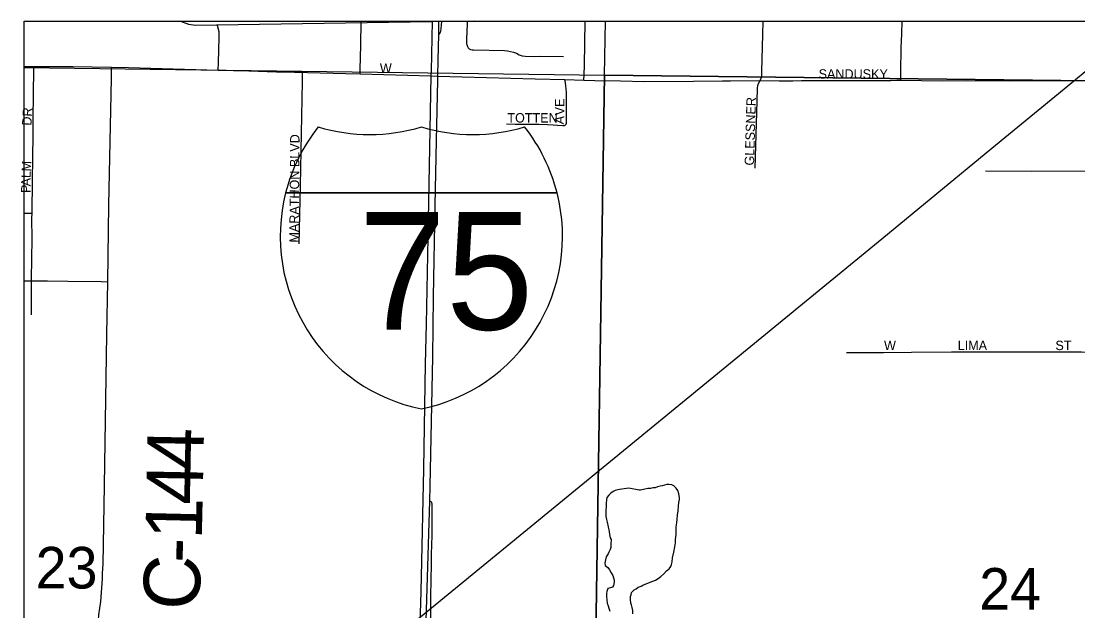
# Model space of a CAD drawing. Extents: x 0 to 68, y 0 to 52.9.
# Drawn here: x 41.101 to 42.505, y 41.224 to 42.008 of the extents above; entities that cross this region are included whole.
import ezdxf

# ---------------------------------------------------------------- set-up
doc = ezdxf.new("R2010")
doc.units = 0
for name, color, linetype in [('Default', 7, 'Continuous'), ('GM_X_County_Road', 7, 'Continuous'), ('GM_X_County_Road_Text', 7, 'Continuous'), ('GM_X_Minor_Lake', 7, 'Continuous'), ('GM_X_Township_Subdivision', 7, 'Continuous'), ('GM_X_Township_Subdivision_Text', 7, 'Continuous')]:
    doc.layers.add(name, color=color, linetype=linetype)

msp = doc.modelspace()

# ---------------------------------------------------------------- linework, layer by layer
at = {"layer": 'Default'}
for p, q in [((41.1051, 32.7683), (41.1051, 42.0083)), ((41.1051, 42.0083), (50.3451, 42.0083)), ((41.4527, 41.7799), (41.8134, 41.7799)), ((41.8134, 41.7799), (41.4527, 41.7799)), ((41.8134, 41.7799), (41.4527, 41.7799))]:
    msp.add_line(p, q, dxfattribs=at)
for points in [[(41.1051, 40.7827), (41.6098, 41.1982), (42.245, 41.7191), (42.3911, 41.8395), (42.4919, 41.9222), (42.5252, 41.9497), (42.5507, 41.971), (42.5671, 41.9855), (42.5837, 42.0005), (42.5919, 42.0083)], [(41.5517, 41.9382), (41.5517, 41.9445), (41.5525, 41.9761), (41.553, 42.0083)], [(41.6308, 41.1995), (41.6324, 41.2337), (41.6333, 41.2697), (41.6363, 41.4133), (41.6387, 41.5527), (41.6397, 41.6056), (41.642, 41.7205), (41.6462, 41.9354), (41.6463, 41.942), (41.6477, 42.0083)], [(41.655, 41.9298), (41.6551, 41.9353), (41.6555, 41.9562), (41.6563, 41.9905), (41.6564, 42.0083)], [(41.6563, 41.9905), (41.6572, 41.9913), (41.6576, 41.9921), (41.6579, 41.9925), (41.6581, 41.993), (41.6583, 41.9935), (41.6585, 41.9941), (41.6587, 41.995), (41.6589, 41.9958), (41.6592, 41.9974), (41.6594, 41.9988), (41.6598, 42.0027), (41.6602, 42.0083)], [(41.6938, 42.0081), (41.6938, 42.0048), (41.6929, 41.9842), (41.693, 41.98), (41.6932, 41.9781), (41.6934, 41.9771), (41.6937, 41.9761), (41.6942, 41.9745), (41.6947, 41.9736), (41.6954, 41.9727), (41.6965, 41.9716), (41.6973, 41.9711), (41.6985, 41.9706), (41.7004, 41.9703), (41.7025, 41.9701), (41.7436, 41.9694), (41.7476, 41.9688), (41.7556, 41.9671), (41.7593, 41.9655), (41.763, 41.9635), (41.7668, 41.9622), (41.7708, 41.9617), (41.783, 41.9613), (41.7913, 41.9615), (41.822, 41.9611)], [(41.8489, 41.9297), (41.8492, 41.9372), (41.8497, 41.9495), (41.8506, 42.0083)], [(43.2047, 42.0083), (43.2028, 41.9209), (41.8762, 41.9363), (41.8775, 42.0083)], [(42.0833, 41.9292), (42.0845, 41.9326), (42.0852, 41.9356), (42.0855, 41.9381), (42.0856, 41.9413), (42.0868, 41.9903), (42.0872, 42.0083)], [(42.27, 41.9296), (42.2702, 41.9407), (42.2707, 41.9729), (42.2713, 41.9914), (42.2718, 42.0083)], [(41.1051, 41.9468), (41.8762, 41.9363), (41.8559, 40.6193), (41.1051, 40.6295)], [(41.4708, 41.7124), (41.4725, 41.7897), (41.475, 41.9281), (41.4752, 41.9403)], [(41.5327, 41.9387), (41.5517, 41.9382)], [(41.5517, 41.9382), (41.6462, 41.9354), (41.6551, 41.9353), (41.7844, 41.9316), (41.8235, 41.9306)], [(41.6441, 41.3706), (41.6447, 41.3903), (41.6482, 41.5619), (41.649, 41.6416), (41.6515, 41.7634), (41.6533, 41.8495), (41.655, 41.9298)], [(41.7461, 41.8716), (41.758, 41.8713), (41.7791, 41.8713), (41.7896, 41.8713), (41.8006, 41.8708), (41.808, 41.8703), (41.8138, 41.8698), (41.8212, 41.8694), (41.8223, 41.8694), (41.8232, 41.8696), (41.8239, 41.8699), (41.8246, 41.8703), (41.8249, 41.8707), (41.8253, 41.8712), (41.8255, 41.8718), (41.8257, 41.8724), (41.8258, 41.8731), (41.8259, 41.8745), (41.8259, 41.8761), (41.8259, 41.8815), (41.8258, 41.9017), (41.8257, 41.9136), (41.8254, 41.9179), (41.8251, 41.9221), (41.8245, 41.9262), (41.8235, 41.9306)], [(41.8235, 41.9306), (41.8489, 41.9297)], [(41.8489, 41.9297), (41.8634, 41.9293), (41.8976, 41.9288)], [(41.8976, 41.9288), (41.929, 41.9282), (41.9946, 41.9285), (42.0332, 41.9289)], [(42.0332, 41.9289), (42.0438, 41.929), (42.0833, 41.9292)], [(42.0765, 41.8127), (42.0791, 41.9021), (42.0795, 41.9192), (42.08, 41.9227), (42.0811, 41.9255), (42.0833, 41.9292)], [(42.0833, 41.9292), (42.1085, 41.9288), (42.1266, 41.929), (42.1381, 41.9292), (42.1952, 41.9294), (42.2568, 41.9294), (42.2646, 41.9296), (42.27, 41.9296)], [(42.27, 41.9296), (42.325, 41.9289), (42.3571, 41.9294), (42.4144, 41.9291), (42.5123, 41.9293), (42.5503, 41.9291)], [(42.3827, 41.8091), (42.4441, 41.8088), (42.548, 41.8093)], [(42.1979, 41.5678), (42.2225, 41.5677), (42.2471, 41.5678), (42.2841, 41.5681), (42.3375, 41.5689), (42.4073, 41.5685), (42.51, 41.5687), (42.5299, 41.5684), (42.544, 41.5683)], [(41.6405, 41.2397), (41.6441, 41.3706)], [(41.6456, 41.2439), (41.6465, 41.2866), (41.6467, 41.2953), (41.6466, 41.2996), (41.6472, 41.3244), (41.6475, 41.3654), (41.6473, 41.3667), (41.6471, 41.3676), (41.6468, 41.3683), (41.6464, 41.3688), (41.6459, 41.3695), (41.6453, 41.3699), (41.6441, 41.3706)], [(41.6392, 41.2065), (41.6393, 41.2074), (41.6394, 41.2109), (41.6405, 41.2397)], [(41.6456, 41.2117), (41.6454, 41.2176), (41.6456, 41.233), (41.6456, 41.2428), (41.6456, 41.2439)]]:
    msp.add_lwpolyline(points, dxfattribs=at)
msp.add_lwpolyline([(41.8762, 41.9363), (43.2028, 41.9209), (43.183, 40.6024), (41.8559, 40.6193)], close=True, dxfattribs=at)
for centre, start, end in [((41.6799, 41.7224), 141.669, 165.8066), ((41.5645, 42.0919), 253.0091, 286.9909), ((41.7015, 42.0919), 253.0091, 286.9909), ((41.5862, 41.7224), 14.1934, 38.331), ((41.6799, 41.7224), 165.8066, 258.463), ((41.5862, 41.7224), 281.537, 14.1934)]:
    msp.add_arc(centre, 0.2344, start, end, dxfattribs=at)
at = {"layer": 'GM_X_County_Road'}
for points in [[(41.1051, 41.9482), (41.1179, 41.9481)], [(41.1179, 41.9481), (41.1701, 41.9479), (41.2214, 41.9472)], [(41.2164, 41.6619), (41.2179, 41.7639), (41.2211, 41.932), (41.2214, 41.9472)], [(41.2214, 41.9472), (41.2439, 41.9468), (41.3632, 41.943)], [(41.3632, 41.943), (41.4037, 41.9421), (41.4406, 41.941), (41.45, 41.9408)], [(41.45, 41.9408), (41.4645, 41.9405)], [(41.4645, 41.9405), (41.4752, 41.9403)], [(41.4752, 41.9403), (41.4816, 41.9402), (41.5327, 41.9387)], [(41.1841, 41.1549), (41.1872, 41.1611), (41.1888, 41.1647), (41.1919, 41.1728), (41.1939, 41.1785), (41.1964, 41.1855), (41.1982, 41.1914), (41.2019, 41.2056), (41.2043, 41.2166), (41.2046, 41.2192), (41.2072, 41.2368), (41.2092, 41.2671), (41.2094, 41.2743), (41.21, 41.2866), (41.2122, 41.3909), (41.2153, 41.5917), (41.2164, 41.6619)]]:
    msp.add_lwpolyline(points, dxfattribs=at)
at = {"layer": 'GM_X_Minor_Lake'}
for points in [[(41.9225, 41.385), (41.9085, 41.3873), (41.9055, 41.3869), (41.9024, 41.3864), (41.8994, 41.386), (41.8964, 41.3856), (41.8939, 41.3851), (41.8904, 41.3842), (41.8878, 41.3832), (41.8848, 41.3808), (41.8822, 41.3783), (41.8796, 41.3749), (41.8791, 41.3719), (41.8785, 41.3674), (41.8784, 41.3634), (41.8783, 41.3573), (41.8781, 41.3503), (41.879, 41.3458), (41.88, 41.3423), (41.8827, 41.3297), (41.8831, 41.3257), (41.8841, 41.3216), (41.885, 41.3191), (41.8849, 41.3131), (41.8848, 41.3086), (41.8838, 41.3061), (41.8822, 41.3026), (41.8811, 41.3001), (41.8785, 41.2962), (41.8775, 41.2922), (41.8769, 41.2877), (41.8773, 41.2846), (41.8808, 41.2821), (41.8832, 41.279), (41.8851, 41.275), (41.8876, 41.2714), (41.8894, 41.2653), (41.8894, 41.2623), (41.8883, 41.2583), (41.8868, 41.2559), (41.8842, 41.2549), (41.8807, 41.254), (41.8796, 41.25), (41.8791, 41.2475), (41.879, 41.2435), (41.8794, 41.239), (41.8798, 41.2344), (41.8812, 41.2309), (41.8822, 41.2279), (41.8836, 41.2238)], [(41.9696, 41.3094), (41.9707, 41.3149), (41.9708, 41.3194), (41.9714, 41.3259), (41.9715, 41.3309), (41.9716, 41.3359), (41.9723, 41.3414), (41.9729, 41.3464), (41.9735, 41.3514), (41.9741, 41.3574), (41.9747, 41.3634), (41.9753, 41.3684), (41.9759, 41.3724), (41.976, 41.3749), (41.975, 41.38), (41.9736, 41.3845), (41.9717, 41.3876), (41.9687, 41.3906), (41.9658, 41.3917), (41.9618, 41.3923), (41.9592, 41.3923), (41.9562, 41.3914), (41.9532, 41.3904), (41.9502, 41.39), (41.9466, 41.3891), (41.9436, 41.3881), (41.9406, 41.3877), (41.9376, 41.3872), (41.9341, 41.3868), (41.924, 41.385), (41.923, 41.385), (41.9225, 41.385)], [(41.9141, 41.2202), (41.9142, 41.2247), (41.9133, 41.2288), (41.9124, 41.2323), (41.9114, 41.2348), (41.911, 41.2393), (41.9111, 41.2433), (41.9116, 41.2458), (41.9122, 41.2488), (41.9158, 41.2523), (41.9183, 41.2537), (41.9209, 41.2557), (41.9249, 41.2571), (41.9274, 41.2586), (41.9305, 41.26), (41.9406, 41.2638), (41.9441, 41.2652), (41.9477, 41.2672), (41.9512, 41.2701), (41.9553, 41.2735), (41.9589, 41.2775), (41.9625, 41.2804), (41.9646, 41.2834), (41.9656, 41.2859), (41.9662, 41.2894), (41.9668, 41.2949), (41.9685, 41.3024), (41.9696, 41.3094)]]:
    msp.add_lwpolyline(points, dxfattribs=at)
at = {"layer": 'GM_X_Township_Subdivision'}
for points in [[(41.7038, 42.0083), (41.3323, 42.0024), (41.3242, 42.0037), (41.3122, 42.0083)], [(41.3632, 41.943), (41.3635, 41.953), (41.3644, 41.9871), (41.3644, 41.9942), (41.3621, 42.0026)], [(41.1157, 41.753), (41.1161, 41.797), (41.1171, 41.8568), (41.1172, 41.8691), (41.1177, 41.92), (41.1179, 41.9354), (41.1179, 41.9481)], [(41.1051, 41.7531), (41.1157, 41.753)], [(41.115, 41.6631), (41.1149, 41.6659), (41.1157, 41.7191), (41.1156, 41.7462), (41.1157, 41.753)], [(41.1051, 41.6632), (41.115, 41.6631)], [(41.1151, 41.618), (41.1152, 41.6454), (41.115, 41.6631)], [(41.115, 41.6631), (41.1363, 41.6629), (41.1633, 41.6626), (41.2077, 41.662), (41.2164, 41.6619)]]:
    msp.add_lwpolyline(points, dxfattribs=at)

# ---------------------------------------------------------------- texts
at = {"layer": 'Default'}
for s, height, rotation, p in [('W', 0.0125, 0, (41.5779, 41.9395)), ('SANDUSKY', 0.0125, 0, (42.1609, 41.9318)), ('E', 0.0125, 90.5464, (41.823, 41.8943)), ('GLESSNER', 0.0125, 88.3643, (42.075, 41.8162)), ('TOTTEN', 0.0125, 0, (41.7473, 41.8735)), ('V', 0.0125, 91.3787, (41.8232, 41.8833)), ('A', 0.0125, 85.142, (41.8222, 41.8709)), ('MARATHON BLVD', 0.0125, 89.5306, (41.47, 41.7139)), ('W', 0.0125, 0, (42.2478, 41.571)), ('LIMA', 0.0125, 0, (42.3457, 41.571)), ('ST', 0.0125, 0, (42.4755, 41.571)), ('23', 0.05525, 0, (41.1205, 41.2541)), ('24', 0.05525, 0, (42.3743, 41.226))]:
    msp.add_text(s, height=height, rotation=rotation, dxfattribs=at).set_placement(p)
msp.add_text('75', height=0.15625, dxfattribs=at).set_placement((41.5495, 41.5982))
at = {"layer": 'GM_X_County_Road_Text'}
for s, rotation, p in [('4', 88.9116, (41.3432, 41.4113)), ('4', 88.8582, (41.3423, 41.365)), ('1', 88.6711, (41.3412, 41.3186)), ('-', 88.3544, (41.3403, 41.2873)), ('C', 87.2395, (41.3373, 41.2242))]:
    msp.add_text(s, height=0.075, rotation=rotation, dxfattribs=at).set_placement(p)
at = {"layer": 'GM_X_Township_Subdivision_Text'}
for s, rotation, p in [('DR', 86.9884, (41.1148, 41.8691)), ('M', 87.5223, (41.1142, 41.8083)), ('L', 87.7869, (41.1138, 41.7995)), ('P', 89.7541, (41.1137, 41.7799)), ('A', 89.4754, (41.1137, 41.7886))]:
    msp.add_text(s, height=0.0125, rotation=rotation, dxfattribs=at).set_placement(p)

doc.saveas('drawing.dxf')
